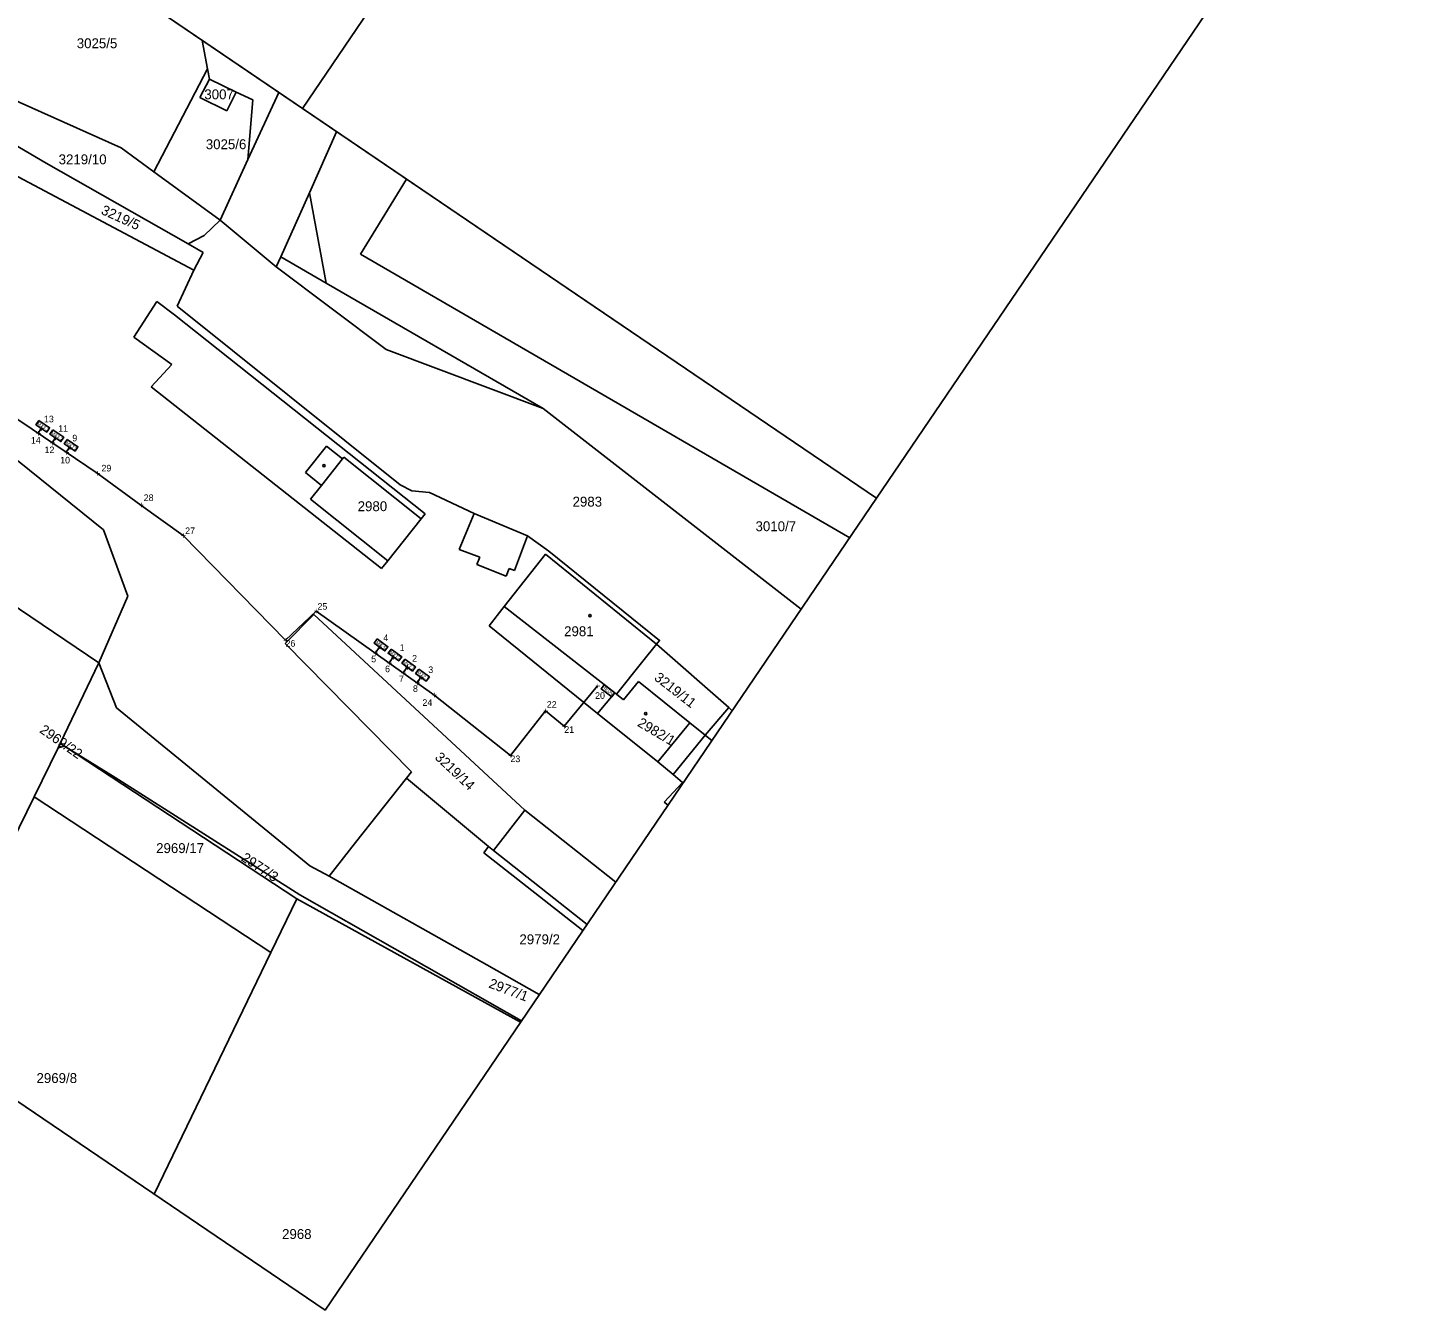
# Model space of a CAD drawing. Extents: x -621058 to -620110, y -1122807 to -1122030.
# Drawn here: x -620321.3 to -620109.5, y -1122806.7 to -1122612.7 of the extents above; entities that cross this region are included whole.
import ezdxf

# ---------------------------------------------------------------- set-up
doc = ezdxf.new("R2010")
doc.units = 0
for name, color, linetype in [('060601_EOV', 7, 'Continuous'), ('BODY', 7, 'Continuous'), ('BODY POPIS', 7, 'Continuous'), ('RÁMY', 7, 'Continuous'), ('Vrstva 53', 7, 'Continuous'), ('Vrstva 55', 7, 'Continuous'), ('Vrstva 56', 7, 'Continuous'), ('Vrstva 57', 7, 'Continuous')]:
    doc.layers.add(name, color=color, linetype=linetype)

msp = doc.modelspace()

# ---------------------------------------------------------------- linework, layer by layer
at = {"layer": '060601_EOV'}
for p, q in [((-620319.3, -1122673.26), (-620319.79, -1122673.98)), ((-620317.15, -1122674.7), (-620317.65, -1122675.43)), ((-620315.01, -1122676.14), (-620315.51, -1122676.88)), ((-620268.13, -1122706.35), (-620268.77, -1122707.26)), ((-620266.04, -1122707.88), (-620266.66, -1122708.76)), ((-620266.04, -1122707.88), (-620266.04, -1122707.89)), ((-620263.95, -1122709.4), (-620264.56, -1122710.26)), ((-620263.95, -1122709.4), (-620263.95, -1122709.41)), ((-620261.86, -1122710.92), (-620262.45, -1122711.75)), ((-620261.86, -1122710.92), (-620261.87, -1122710.93))]:
    msp.add_line(p, q, dxfattribs=at)
msp.add_lwpolyline([(-620235.16, -1122712.24), (-620240.17, -1122718.34), (-620243.03, -1122716), (-620248.32, -1122722.77), (-620259.89, -1122713.57), (-620277.71, -1122700.9), (-620282.35, -1122705.3), (-620297.82, -1122689.49), (-620304.22, -1122684.86), (-620310.82, -1122680.06), (-620322.23, -1122672.32), (-620343.18, -1122658.46), (-620368.5, -1122642.9), (-620411.56, -1122614.92), (-620424.16, -1122607.09), (-620443.53, -1122595), (-620456.11, -1122587.12), (-620447.82, -1122572.96), (-620450.95, -1122571.45), (-620470.59, -1122561.48), (-620499.61, -1122545.57), (-620522.04, -1122531.47), (-620538.89, -1122521.21), (-620599.21, -1122483.22)], dxfattribs=at)
for points in [[(-620319.68, -1122672.05), (-620318.04, -1122673.16), (-620318.47, -1122673.81), (-620320.12, -1122672.7)], [(-620317.54, -1122673.49), (-620315.89, -1122674.6), (-620316.33, -1122675.26), (-620317.98, -1122674.14)], [(-620315.39, -1122674.94), (-620313.75, -1122676.05), (-620314.19, -1122676.7), (-620315.83, -1122675.59)], [(-620268.47, -1122705.13), (-620266.86, -1122706.3), (-620267.32, -1122706.94), (-620268.93, -1122705.77)], [(-620266.38, -1122706.65), (-620264.77, -1122707.83), (-620265.23, -1122708.46), (-620266.84, -1122707.29)], [(-620264.29, -1122708.18), (-620262.68, -1122709.35), (-620263.14, -1122709.98), (-620264.75, -1122708.81)], [(-620262.2, -1122709.7), (-620260.59, -1122710.87), (-620261.05, -1122711.51), (-620262.66, -1122710.34)], [(-620234.12, -1122712.05), (-620232.51, -1122713.28), (-620232.99, -1122713.9), (-620234.59, -1122712.68)]]:
    msp.add_lwpolyline(points, close=True, dxfattribs=at)
at = {"layer": 'RÁMY'}
for points in [[(-620974.7, -1122152.91), (-620192.94, -1122683.83), (-620276.37, -1122806.68), (-621058.13, -1122275.76)], [(-620887.83, -1122211.9), (-620192.94, -1122683.83), (-620276.37, -1122806.68), (-620971.26, -1122334.75)], [(-620283.23, -1122443), (-620196.37, -1122501.99), (-620279.8, -1122624.84), (-620366.66, -1122565.85)], [(-620196.37, -1122501.99), (-620109.51, -1122560.98), (-620192.94, -1122683.83), (-620279.8, -1122624.84)]]:
    msp.add_lwpolyline(points, close=True, dxfattribs=at)
at = {"layer": 'Vrstva 53'}
for p, q in [((-620347.83, -1122621.96), (-620296.23, -1122649.3)), ((-620335.09, -1122623.49), (-620318.55, -1122633.1)), ((-620318.55, -1122633.1), (-620297.09, -1122645.35)), ((-620297.09, -1122645.35), (-620294.83, -1122646.64)), ((-620294.83, -1122646.64), (-620296.23, -1122649.3)), ((-620298.73, -1122654.76), (-620296.23, -1122649.3)), ((-620301.83, -1122654.06), (-620305.28, -1122659.46)), ((-620299.15, -1122656.1), (-620301.83, -1122654.06)), ((-620299.15, -1122656.1), (-620261.22, -1122686.17)), ((-620298.73, -1122654.76), (-620265, -1122681.82)), ((-620299.56, -1122663.58), (-620305.28, -1122659.46)), ((-620299.56, -1122663.58), (-620302.66, -1122666.96)), ((-620267.81, -1122694.49), (-620302.66, -1122666.96)), ((-620309.9, -1122688.62), (-620334.71, -1122668.63)), ((-620265, -1122681.82), (-620263.22, -1122682.69)), ((-620263.22, -1122682.69), (-620260.55, -1122682.94)), ((-620260.55, -1122682.94), (-620253.83, -1122686.12)), ((-620253.83, -1122686.12), (-620245.73, -1122689.53)), ((-620261.82, -1122686.93), (-620266.86, -1122693.31)), ((-620261.82, -1122686.93), (-620261.22, -1122686.17)), ((-620306.2, -1122698.65), (-620309.9, -1122688.62)), ((-620245.73, -1122689.53), (-620242.51, -1122691.82)), ((-620249.26, -1122700.23), (-620243.01, -1122692.32)), ((-620226.24, -1122705.93), (-620243.01, -1122692.32)), ((-620267.81, -1122694.49), (-620266.86, -1122693.31)), ((-620310.57, -1122708.76), (-620306.2, -1122698.65)), ((-620251.53, -1122703.16), (-620249.26, -1122700.23)), ((-620278.07, -1122701.42), (-620282.38, -1122705.84)), ((-620278.07, -1122701.42), (-620246.12, -1122731.05)), ((-620235.14, -1122716.41), (-620251.53, -1122703.16)), ((-620263.28, -1122725.23), (-620282.38, -1122705.84)), ((-620226.24, -1122705.93), (-620228.28, -1122708.48)), ((-620226.24, -1122705.93), (-620215.29, -1122715.52)), ((-620307.94, -1122715.53), (-620310.57, -1122708.76)), ((-620228.28, -1122708.48), (-620232.27, -1122713.47)), ((-620231.2, -1122714.35), (-620228.95, -1122711.56)), ((-620228.95, -1122711.56), (-620221.19, -1122717.82)), ((-620232.51, -1122713.28), (-620235.14, -1122716.41)), ((-620232.27, -1122713.47), (-620232.51, -1122713.28)), ((-620232.27, -1122713.47), (-620231.2, -1122714.35)), ((-620278.65, -1122739.48), (-620307.94, -1122715.53)), ((-620218.86, -1122719.7), (-620215.29, -1122715.52)), ((-620226.02, -1122723.74), (-620235.14, -1122716.41)), ((-620221.19, -1122717.82), (-620218.86, -1122719.7)), ((-620218.86, -1122719.7), (-620223.68, -1122725.62)), ((-620226.02, -1122723.74), (-620223.68, -1122725.62)), ((-620271.78, -1122735.94), (-620264.06, -1122726.18)), ((-620263.28, -1122725.23), (-620264.06, -1122726.18)), ((-620251.62, -1122736.54), (-620264.06, -1122726.18)), ((-620223.68, -1122725.62), (-620222.3, -1122726.83)), ((-620222.3, -1122726.83), (-620225.04, -1122729.85)), ((-620225.04, -1122729.85), (-620224.48, -1122730.28)), ((-620250.89, -1122737.15), (-620246.12, -1122731.05)), ((-620246.12, -1122731.05), (-620232.4, -1122741.94)), ((-620275.74, -1122741.01), (-620271.78, -1122735.94)), ((-620252.35, -1122737.47), (-620251.62, -1122736.54)), ((-620250.89, -1122737.15), (-620251.62, -1122736.54)), ((-620237.38, -1122749.27), (-620252.35, -1122737.47)), ((-620278.65, -1122739.48), (-620275.74, -1122741.01)), ((-620251.9, -1122754.44), (-620275.74, -1122741.01)), ((-620243.95, -1122758.95), (-620251.9, -1122754.44))]:
    msp.add_line(p, q, dxfattribs=at)
msp.add_lwpolyline([(-620242.51, -1122691.82), (-620225.75, -1122705.35), (-620226.24, -1122705.93)], dxfattribs=at)
at = {"layer": 'Vrstva 55'}
for p, q in [((-620294.15, -1122618.83), (-620294.94, -1122614.56)), ((-620333.59, -1122619.01), (-620307.23, -1122630.79)), ((-620294.15, -1122618.83), (-620302.25, -1122634.43)), ((-620295.29, -1122623.2), (-620293.86, -1122620.43)), ((-620293.86, -1122620.43), (-620294.15, -1122618.83)), ((-620293.86, -1122620.43), (-620289.81, -1122622.36)), ((-620347.83, -1122621.96), (-620296.23, -1122649.3)), ((-620289.81, -1122622.36), (-620291.25, -1122625.22)), ((-620287.29, -1122623.55), (-620289.81, -1122622.36)), ((-620283.38, -1122622.41), (-620288.03, -1122632.56)), ((-620318.55, -1122633.1), (-620335.09, -1122623.49)), ((-620291.25, -1122625.22), (-620295.29, -1122623.2)), ((-620288.03, -1122632.56), (-620287.29, -1122623.55)), ((-620278.72, -1122637.63), (-620274.61, -1122628.37)), ((-620307.23, -1122630.79), (-620302.25, -1122634.43)), ((-620297.09, -1122645.35), (-620318.55, -1122633.1)), ((-620292.25, -1122641.75), (-620288.03, -1122632.56)), ((-620302.25, -1122634.43), (-620301.71, -1122634.83)), ((-620301.71, -1122634.83), (-620292.25, -1122641.75)), ((-620264.06, -1122635.53), (-620271, -1122646.92)), ((-620283.08, -1122647.29), (-620278.72, -1122637.63)), ((-620292.25, -1122641.75), (-620294.63, -1122644.08)), ((-620292.25, -1122641.75), (-620283.77, -1122648.8)), ((-620294.63, -1122644.08), (-620297.09, -1122645.35)), ((-620297.09, -1122645.35), (-620294.83, -1122646.64)), ((-620294.83, -1122646.64), (-620296.23, -1122649.3)), ((-620283.77, -1122648.8), (-620283.08, -1122647.29)), ((-620271, -1122646.92), (-620196.99, -1122689.8)), ((-620298.73, -1122654.76), (-620296.23, -1122649.3)), ((-620283.77, -1122648.8), (-620267.12, -1122661.31)), ((-620301.83, -1122654.06), (-620305.28, -1122659.46)), ((-620299.15, -1122656.1), (-620301.83, -1122654.06)), ((-620261.22, -1122686.17), (-620299.15, -1122656.1)), ((-620265, -1122681.82), (-620298.73, -1122654.76)), ((-620305.28, -1122659.46), (-620299.56, -1122663.58)), ((-620267.12, -1122661.31), (-620243.36, -1122670.23)), ((-620299.56, -1122663.58), (-620302.66, -1122666.96)), ((-620302.66, -1122666.96), (-620267.81, -1122694.49)), ((-620309.9, -1122688.62), (-620334.71, -1122668.63)), ((-620368.46, -1122669.58), (-620310.57, -1122708.76)), ((-620243.36, -1122670.23), (-620204.33, -1122700.61)), ((-620265, -1122681.82), (-620263.22, -1122682.69)), ((-620263.22, -1122682.69), (-620260.55, -1122682.94)), ((-620260.55, -1122682.94), (-620253.83, -1122686.12)), ((-620253.83, -1122686.12), (-620245.73, -1122689.53)), ((-620266.86, -1122693.31), (-620261.82, -1122686.93)), ((-620261.82, -1122686.93), (-620261.22, -1122686.17)), ((-620306.2, -1122698.65), (-620309.9, -1122688.62)), ((-620245.73, -1122689.53), (-620242.51, -1122691.82)), ((-620249.26, -1122700.23), (-620243.01, -1122692.32)), ((-620243.01, -1122692.32), (-620226.24, -1122705.93)), ((-620225.75, -1122705.35), (-620242.51, -1122691.82)), ((-620267.81, -1122694.49), (-620266.86, -1122693.31)), ((-620310.57, -1122708.76), (-620306.2, -1122698.65)), ((-620251.53, -1122703.16), (-620249.26, -1122700.23)), ((-620278.07, -1122701.42), (-620282.38, -1122705.84)), ((-620246.12, -1122731.05), (-620278.07, -1122701.42)), ((-620235.14, -1122716.41), (-620251.53, -1122703.16)), ((-620282.38, -1122705.84), (-620263.28, -1122725.23)), ((-620226.24, -1122705.93), (-620228.28, -1122708.48)), ((-620225.75, -1122705.35), (-620226.24, -1122705.93)), ((-620215.29, -1122715.52), (-620226.24, -1122705.93)), ((-620310.57, -1122708.76), (-620316.42, -1122720.94)), ((-620310.57, -1122708.76), (-620307.94, -1122715.53)), ((-620228.28, -1122708.48), (-620232.27, -1122713.47)), ((-620231.2, -1122714.35), (-620228.95, -1122711.56)), ((-620228.95, -1122711.56), (-620221.19, -1122717.82)), ((-620232.51, -1122713.28), (-620235.14, -1122716.41)), ((-620232.27, -1122713.47), (-620232.51, -1122713.28)), ((-620232.27, -1122713.47), (-620231.2, -1122714.35)), ((-620307.94, -1122715.53), (-620278.65, -1122739.48)), ((-620218.86, -1122719.7), (-620215.29, -1122715.52)), ((-620214.77, -1122715.98), (-620215.29, -1122715.52)), ((-620235.14, -1122716.41), (-620226.02, -1122723.74)), ((-620221.19, -1122717.82), (-620218.86, -1122719.7)), ((-620223.68, -1122725.62), (-620218.86, -1122719.7)), ((-620218.86, -1122719.7), (-620218.55, -1122719.95)), ((-620218.55, -1122719.95), (-620217.85, -1122720.51)), ((-620320.37, -1122729), (-620316.74, -1122721.6)), ((-620316.74, -1122721.6), (-620316.42, -1122720.94)), ((-620316.74, -1122721.6), (-620315.79, -1122721.36)), ((-620316.42, -1122720.94), (-620315.79, -1122721.36)), ((-620308.1, -1122726.09), (-620315.79, -1122721.36)), ((-620315.79, -1122721.36), (-620280.66, -1122744.45)), ((-620226.02, -1122723.74), (-620223.68, -1122725.62)), ((-620280.18, -1122743.84), (-620308.1, -1122726.09)), ((-620271.78, -1122735.94), (-620264.06, -1122726.18)), ((-620263.28, -1122725.23), (-620264.06, -1122726.18)), ((-620251.62, -1122736.54), (-620264.06, -1122726.18)), ((-620223.68, -1122725.62), (-620222.3, -1122726.83)), ((-620222.3, -1122726.83), (-620225.04, -1122729.85)), ((-620222.3, -1122726.83), (-620222.2, -1122726.91)), ((-620337.36, -1122763.66), (-620320.37, -1122729)), ((-620320.37, -1122729), (-620284.57, -1122752.56)), ((-620225.04, -1122729.85), (-620224.48, -1122730.28)), ((-620250.89, -1122737.15), (-620246.12, -1122731.05)), ((-620246.12, -1122731.05), (-620232.4, -1122741.94)), ((-620275.74, -1122741.01), (-620271.78, -1122735.94)), ((-620252.35, -1122737.47), (-620251.62, -1122736.54)), ((-620250.89, -1122737.15), (-620251.62, -1122736.54)), ((-620237.38, -1122749.27), (-620252.35, -1122737.47)), ((-620278.65, -1122739.48), (-620275.74, -1122741.01)), ((-620275.74, -1122741.01), (-620251.9, -1122754.44)), ((-620280.66, -1122744.45), (-620284.57, -1122752.56)), ((-620280.66, -1122744.45), (-620246.8, -1122763.14)), ((-620280.18, -1122743.84), (-620246.65, -1122762.93)), ((-620284.57, -1122752.56), (-620302.21, -1122789.13)), ((-620251.9, -1122754.44), (-620243.95, -1122758.95))]:
    msp.add_line(p, q, dxfattribs=at)
at = {"layer": 'Vrstva 56'}
for p, q in [((-620276.18, -1122651.26), (-620278.72, -1122637.63)), ((-620283.08, -1122647.29), (-620276.18, -1122651.26)), ((-620276.18, -1122651.26), (-620243.36, -1122670.23)), ((-620279.35, -1122679.94), (-620276.17, -1122675.94)), ((-620276.17, -1122675.94), (-620273.73, -1122677.87)), ((-620273.73, -1122677.87), (-620273.55, -1122677.64)), ((-620273.55, -1122677.64), (-620261.82, -1122686.93)), ((-620276.91, -1122681.88), (-620273.73, -1122677.87)), ((-620276.91, -1122681.88), (-620279.35, -1122679.94)), ((-620278.56, -1122683.97), (-620276.91, -1122681.88)), ((-620266.86, -1122693.31), (-620278.56, -1122683.97)), ((-620253.83, -1122686.12), (-620256.06, -1122691.57)), ((-620245.73, -1122689.53), (-620247.73, -1122694.76)), ((-620256.06, -1122691.57), (-620252.97, -1122692.73)), ((-620252.97, -1122692.73), (-620253.4, -1122693.88)), ((-620253.4, -1122693.88), (-620248.99, -1122695.65)), ((-620248.99, -1122695.65), (-620248.5, -1122694.45)), ((-620248.5, -1122694.45), (-620247.73, -1122694.76)), ((-620249.26, -1122700.23), (-620232.51, -1122713.28)), ((-620226.02, -1122723.74), (-620221.19, -1122717.82)), ((-620236.73, -1122748.32), (-620250.89, -1122737.15))]:
    msp.add_line(p, q, dxfattribs=at)
at = {"layer": 'Vrstva 57'}
for centre in [(-620276.54, -1122678.91), (-620236.29, -1122701.58), (-620227.84, -1122716.43)]:
    msp.add_circle(centre, 0.175, dxfattribs=at)

# ---------------------------------------------------------------- texts
at = {"layer": '060601_EOV'}
for s, rotation, p in [('MX3.1', 326.029, (-620319.98, -1122672.65)), ('MX3.2', 326.029, (-620317.88, -1122674.06)), ('MXT3', 326.029, (-620315.64, -1122675.58)), ('MX S', 323.9143, (-620268.71, -1122705.77)), ('MXT2', 323.9143, (-620266.67, -1122707.26)), ('MX2.2', 323.9143, (-620264.65, -1122708.74)), ('MX2.1', 323.9143, (-620262.49, -1122710.31)), ('REOV', 322.5799, (-620234.47, -1122712.52))]:
    msp.add_text(s, height=0.5, rotation=rotation, dxfattribs=at).set_placement(p)
at = {"layer": 'BODY'}
for p in [(-620319.63, -1122673.76), (-620320.12, -1122674.48), (-620317.98, -1122675.93), (-620317.49, -1122675.2), (-620315.84, -1122677.38), (-620315.34, -1122676.64), (-620311.15, -1122680.56), (-620304.56, -1122685.36), (-620298.15, -1122689.99), (-620278.05, -1122701.4), (-620282.68, -1122705.8), (-620269.1, -1122707.76), (-620268.46, -1122706.85), (-620267, -1122709.26), (-620266.38, -1122708.39), (-620266.37, -1122708.38), (-620264.29, -1122709.91), (-620264.28, -1122709.9), (-620264.89, -1122710.76), (-620262.78, -1122712.25), (-620262.2, -1122711.43), (-620262.19, -1122711.42), (-620260.22, -1122714.07), (-620235.49, -1122712.74), (-620243.36, -1122716.5), (-620240.51, -1122718.84), (-620248.65, -1122723.27)]:
    msp.add_text('+', height=1, dxfattribs=at).set_placement(p)
at = {"layer": 'BODY POPIS'}
for s, p in [('13', (-620318.89, -1122672.34)), ('11', (-620316.74, -1122673.78)), ('14', (-620320.87, -1122675.57)), ('9', (-620314.6, -1122675.23)), ('12', (-620318.8, -1122677.01)), ('10', (-620316.44, -1122678.57)), ('29', (-620310.19, -1122679.78)), ('28', (-620303.8, -1122684.26)), ('27', (-620297.53, -1122689.26)), ('25', (-620277.51, -1122700.71)), ('4', (-620267.55, -1122705.45)), ('26', (-620282.35, -1122706.3)), ('1', (-620265.08, -1122706.95)), ('5', (-620269.39, -1122708.66)), ('6', (-620267.29, -1122710.16)), ('2', (-620263.19, -1122708.55)), ('3', (-620260.75, -1122710.29)), ('7', (-620265.18, -1122711.66)), ('8', (-620263.07, -1122713.15)), ('20', (-620235.51, -1122714.19)), ('24', (-620261.63, -1122715.25)), ('22', (-620242.82, -1122715.54)), ('21', (-620240.17, -1122719.34)), ('23', (-620248.32, -1122723.77))]:
    msp.add_text(s, height=1, dxfattribs=at).set_placement(p)
at = {"layer": 'Vrstva 57'}
for s, p in [('3025/5', (-620313.93, -1122615.73)), ('3007', (-620294.63, -1122623.46)), ('3025/6', (-620294.41, -1122631.01)), ('3219/10', (-620316.67, -1122633.3)), ('2983', (-620238.92, -1122685.1)), ('2980', (-620271.43, -1122685.79)), ('3010/7', (-620211.24, -1122688.82)), ('2981', (-620240.2, -1122704.71)), ('2969/17', (-620301.92, -1122737.53)), ('2979/2', (-620246.96, -1122751.33)), ('2969/8', (-620320.02, -1122772.33)), ('2968', (-620282.87, -1122795.93))]:
    msp.add_text(s, height=1.5, dxfattribs=at).set_placement(p)
for s, rotation, p in [('3219/5', 335.5818, (-620310.37, -1122640.76)), ('3219/11', 322.1138, (-620226.69, -1122711.22)), ('2982/1', 329.4, (-620229.23, -1122718.23)), ('2969/22', 324.8459, (-620319.67, -1122719.19)), ('3219/14', 316.8, (-620259.86, -1122723.19)), ('2977/3', 326.397, (-620289.18, -1122738.58)), ('2977/1', 339.3, (-620251.72, -1122757.84))]:
    msp.add_text(s, height=1.5, rotation=rotation, dxfattribs=at).set_placement(p)

doc.saveas('drawing.dxf')
